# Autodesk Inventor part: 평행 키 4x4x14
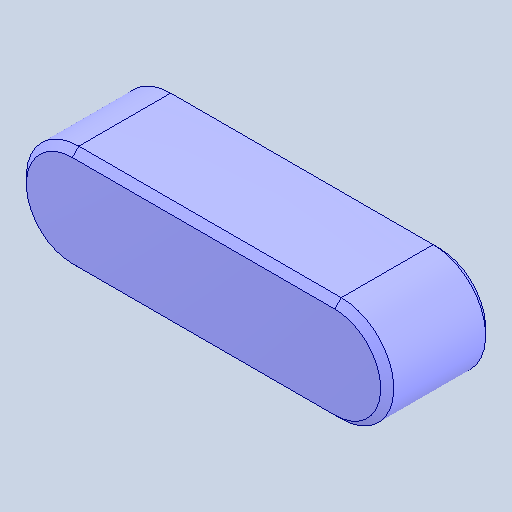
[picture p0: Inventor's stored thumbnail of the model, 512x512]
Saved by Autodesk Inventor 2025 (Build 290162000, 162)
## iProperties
Created: 2026-07
Part Number: 평행 키 4x4x14
Material: 강철, 연강
Document SubType Name: Modeling
Designer: KDI
Density: 7.86 g/cm^3
Appearance: 기본값
Author: jhkim
Revision Number: 1
Sending System: Autodesk Inventor 2027
Preprocessor: ST-DEVELOPER v20.1
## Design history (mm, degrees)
feature "솔리드1"
node "솔리드2"
